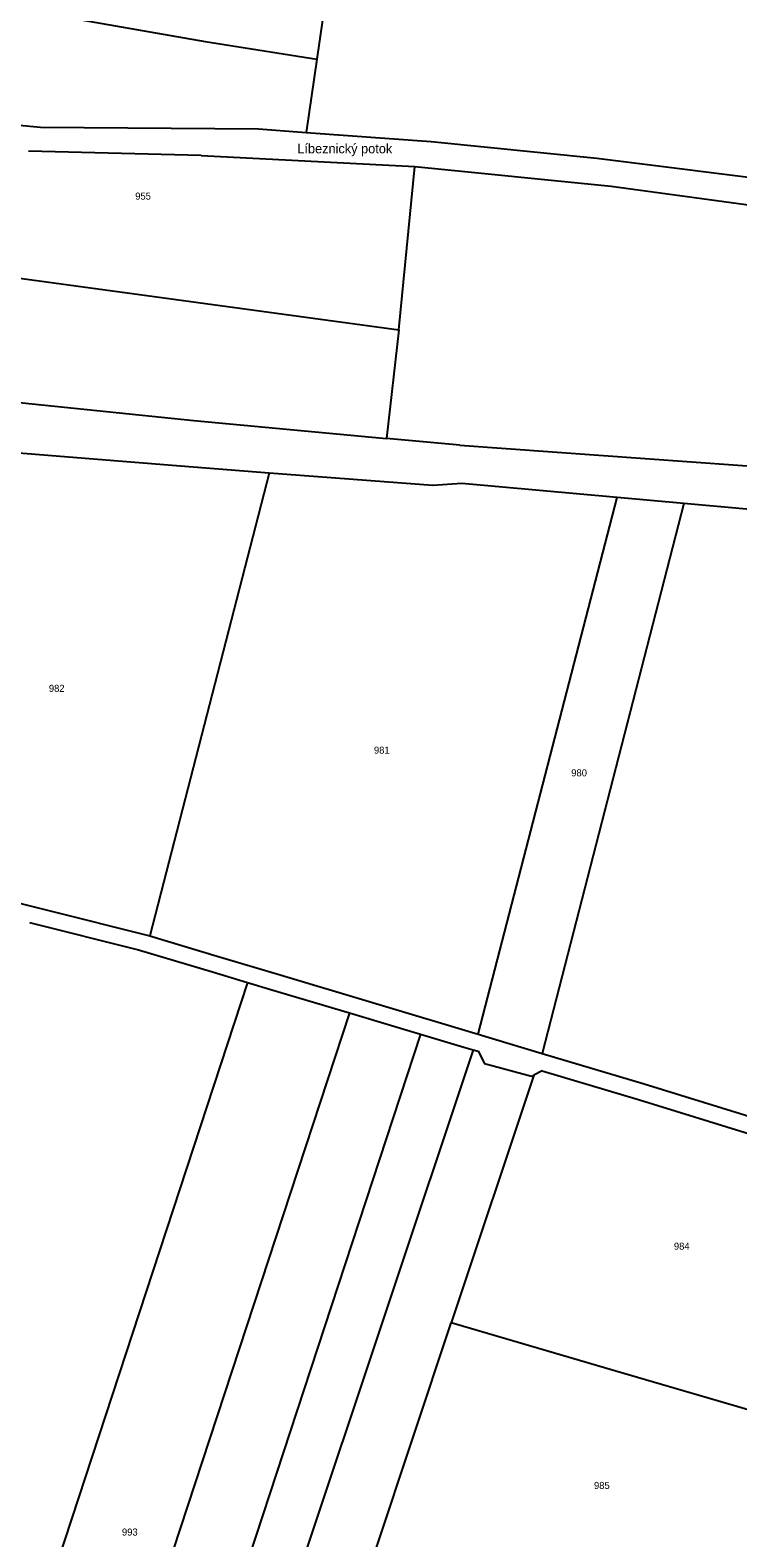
# Model space of a CAD drawing. Extents: x -738131 to -734179, y -1033447 to -1030078.
# Drawn here: x -735400.4 to -735229.5, y -1032530.8 to -1032166.9 of the extents above; entities that cross this region are included whole.
import ezdxf

# ---------------------------------------------------------------- set-up
doc = ezdxf.new("R2010")
doc.units = 0
for name, color, linetype in [('Vrstva 1', 7, 'Continuous'), ('Vrstva 2', 7, 'Continuous'), ('Vrstva 7', 7, 'Continuous')]:
    doc.layers.add(name, color=color, linetype=linetype)

msp = doc.modelspace()

# ---------------------------------------------------------------- linework, layer by layer
at = {"layer": 'Vrstva 1'}
for points in [[(-735305.05, -1031993.87), (-735331.16, -1032173.93)], [(-735388.08, -1032164.46), (-735358.17, -1032169.69)], [(-735358.17, -1032169.69), (-735331.16, -1032173.93)], [(-735331.16, -1032173.93), (-735333.75, -1032191.63)], [(-735427.75, -1032187.53), (-735397.91, -1032190.35)], [(-735397.91, -1032190.35), (-735345.23, -1032190.79)], [(-735345.23, -1032190.79), (-735333.75, -1032191.63)], [(-735333.75, -1032191.63), (-735303.56, -1032193.83)], [(-735303.56, -1032193.83), (-735263.58, -1032197.8)], [(-735359.08, -1032197.16), (-735400.79, -1032196.13)], [(-735359.08, -1032197.16), (-735307.51, -1032199.87)], [(-735263.58, -1032197.8), (-735216.01, -1032203.82)], [(-735311.37, -1032239.24), (-735307.51, -1032199.87)], [(-735307.51, -1032199.87), (-735260.1, -1032204.57)], [(-735260.1, -1032204.57), (-735221.14, -1032209.86)], [(-735443.22, -1032221.33), (-735311.37, -1032239.24)], [(-735311.37, -1032239.24), (-735314.34, -1032265.47)], [(-735407.79, -1032256.34), (-735360.9, -1032261.14)], [(-735360.9, -1032261.14), (-735314.34, -1032265.47)], [(-735296.63, -1032267.12), (-735314.34, -1032265.47)], [(-735296.63, -1032267.12), (-735218.33, -1032272.73)], [(-735364.1, -1032272.18), (-735419.24, -1032267.73)], [(-735342.65, -1032273.82), (-735371.47, -1032385.54)], [(-735342.65, -1032273.82), (-735364.1, -1032272.18)], [(-735303.19, -1032276.84), (-735342.65, -1032273.82)], [(-735296.14, -1032276.36), (-735303.19, -1032276.84)], [(-735258.65, -1032279.75), (-735296.14, -1032276.36)], [(-735292.21, -1032409.27), (-735258.65, -1032279.75)], [(-735242.55, -1032281.2), (-735276.77, -1032413.89)], [(-735242.55, -1032281.2), (-735258.65, -1032279.75)], [(-735215.86, -1032283.61), (-735242.55, -1032281.2)], [(-735446.62, -1032366.68), (-735371.47, -1032385.54)], [(-735400.56, -1032382.31), (-735374.2, -1032388.9)], [(-735371.47, -1032385.54), (-735355.2, -1032390.41)], [(-735374.2, -1032388.9), (-735356.35, -1032394.24)], [(-735355.2, -1032390.41), (-735340.86, -1032394.71)], [(-735356.35, -1032394.24), (-735347.88, -1032396.78)], [(-735340.86, -1032394.71), (-735292.21, -1032409.27)], [(-735347.88, -1032396.78), (-735393.61, -1032536.08)], [(-735347.88, -1032396.78), (-735342, -1032398.54)], [(-735342, -1032398.54), (-735323.32, -1032404.13)], [(-735323.32, -1032404.13), (-735365.95, -1032533.95)], [(-735323.32, -1032404.13), (-735311.77, -1032407.59)], [(-735306.13, -1032409.28), (-735349.23, -1032540.5)], [(-735311.77, -1032407.59), (-735306.13, -1032409.28)], [(-735306.13, -1032409.28), (-735295.7, -1032412.4)], [(-735292.21, -1032409.27), (-735276.77, -1032413.89)], [(-735293.41, -1032413.02), (-735335.58, -1032539.31)], [(-735295.7, -1032412.4), (-735293.41, -1032413.02)], [(-735293.41, -1032413.02), (-735292.22, -1032413.35)], [(-735292.22, -1032413.35), (-735290.67, -1032416.36)], [(-735290.67, -1032416.36), (-735279.37, -1032419.42)], [(-735276.77, -1032413.89), (-735252.16, -1032421.26)], [(-735278.83, -1032419.15), (-735298.74, -1032478.92)], [(-735279.37, -1032419.42), (-735278.83, -1032419.15)], [(-735276.76, -1032418.09), (-735278.83, -1032419.15)], [(-735276.76, -1032418.09), (-735253.29, -1032425.1)], [(-735252.16, -1032421.26), (-735187.07, -1032441.33)], [(-735253.29, -1032425.1), (-735202.27, -1032440.83)], [(-735316.95, -1032533.6), (-735298.74, -1032478.92)], [(-735258.98, -1032490.59), (-735298.74, -1032478.92)], [(-735211.59, -1032504.45), (-735258.98, -1032490.59)]]:
    msp.add_lwpolyline(points, dxfattribs=at)

# ---------------------------------------------------------------- texts
at = {"layer": 'Vrstva 2'}
for s, p in [('955', (-735375.02, -1032207.84)), ('982', (-735395.86, -1032326.64)), ('981', (-735317.39, -1032341.55)), ('980', (-735269.76, -1032347.03)), ('984', (-735244.98, -1032461.27)), ('985', (-735264.27, -1032519.01)), ('993', (-735378.22, -1032530.26))]:
    msp.add_text(s, height=1.7, dxfattribs=at).set_placement(p)
at = {"layer": 'Vrstva 7'}
msp.add_text('Líbeznický potok', height=2.3, dxfattribs=at).set_placement((-735335.88, -1032196.67))

doc.saveas('drawing.dxf')
